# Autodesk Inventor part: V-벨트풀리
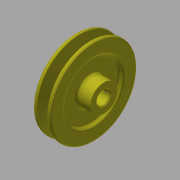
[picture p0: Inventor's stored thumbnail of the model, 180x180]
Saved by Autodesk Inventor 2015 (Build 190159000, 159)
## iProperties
Created: 2015-09
Part Number: V-벨트풀리
Material: 강철, 연강
Document SubType Name: Modeling
Designer: mduedu
Density: 7.86 g/cm^3
Mass: 779.014 g
Surface Area: 277.465 cm^2
Volume: 99.1112 cm^3
Appearance: 강철
Author: mduedu
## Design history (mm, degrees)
sketch "스케치1"
  geometry: L1 (-10, 0)-(10, 0); L2 (-10, 0)-(-10, 48); L3 (-10, 48)-(-5.976, 48); L4 (-5.976, 48)-(-2.154, 35.5); L5 (-2.154, 35.5)-(2.154, 35.5); L6 (2.154, 35.5)-(5.976, 48); L7 (5.976, 48)-(10, 48); L8 (10, 48)-(10, 0); L9 (0, 0)-(0, 35.5); L10 (-10, 43.5)-(10, 43.5); 3 further points
  constraints: 20 end point, 6 point on line, 3 perpendicular, 2 midpoint, 2 parallel, 2 symmetric about line, 1 coincident, 1 collinear, 1 equal length, 1 horizontal, 1 vertical, 1 vertical alignment
  dimensions: "d0" = 20 distance between parallel lines of L8 L2; "d2" = 96 diameter of L3 L1; "d3" = 87 diameter of L10 L1; "d4" = 4.5 distance between parallel lines of L10 L3 (derived); "d5" = 8 distance between parallel lines of L5 L10; "d6" = 9.2 distance of point (4.6, 43.5) point (-4.6, 43.5); "d7" = 34 deg angle of L6 L4
revolve "회전1" sketch "스케치1" stored, may be unused: angle "d8" = 90 deg
sketch "스케치2"
  geometry: C1 r 15 at (0, 0); 1 further point
  constraints: 1 centre point, 1 coincident
  dimensions: "d9" = 30 diameter of C1
extrude "돌출1" join sketch "스케치2" distance "d10" = 11; taper "d11" = 0 deg
fillet "모깎기1" dims "d12" = 1, "d13" = 0.5, "d14" = 2
sketch "스케치3"
  geometry: C1 r 15 at (0, 0) reference; C2 r 32 at (0, 0); 1 further point
  constraints: 1 centre point, 1 coincident
  dimensions: "d15" = 64 diameter of C2
extrude "돌출2" cut sketch "스케치3" distance "d16" = 4; taper "d17" = 0 deg
fillet "모깎기2" dims "d18" = 3
fillet "모깎기3" dims "d19" = 3
fillet "모깎기4" dims "d20" = 3
sketch "스케치4"
  geometry: C1 r 7.5 at (0, 0); 1 further point
  constraints: 1 centre point, 1 coincident
  dimensions: "d21" = 15 diameter of C1
extrude "돌출3" cut sketch "스케치4" stored distance "d22" = 4; taper "d23" = 0 deg
sketch "스케치5"
  geometry: L1 (-2.5, 7.071)-(2.5, 7.071); L2 (2.5, 7.071)-(2.5, 9.8); L3 (2.5, 9.8)-(-2.5, 9.8); L4 (-2.5, 9.8)-(-2.5, 7.071); A1 r 7.5 centre (0, 0) between (-2.5, 7.071) and (2.5, 7.071) reference; 2 further points
  constraints: 8 end point, 3 point on circle, 2 parallel, 1 horizontal, 1 perpendicular, 1 vertical alignment
  dimensions: "d24" = 5 distance of L2.end L3.end; "d26" = 17.3 distance from line of L3 point (0, -7.5)
extrude "돌출4" cut sketch "스케치5" stored distance "d27" = 4; taper "d28" = 0 deg
chamfer "모따기1" distance "d29" = 1; stored, may be unused: second distance "d30" = 2, angle "d31" = 45 deg
node "작업 평면1"
sketch "스케치6"
  geometry: L1 (-11, 15)-(-11, -15) reference; 2 further points
  constraints: 1 horizontal alignment
  dimensions: "d32" = 5 distance from line of point (-6, 0) L1
hole "구멍1" sketch "스케치6" at (-6, 0) diameter "d33" = 3.242; stored, may be unused: countersink angle "d37" = 90 deg, drill point angle "d39" = 118 deg; dims "d34" = 6, "d35" = 4, "d36" = 2, "d38" = 8
node "솔리드1"
mirror "대칭1"
